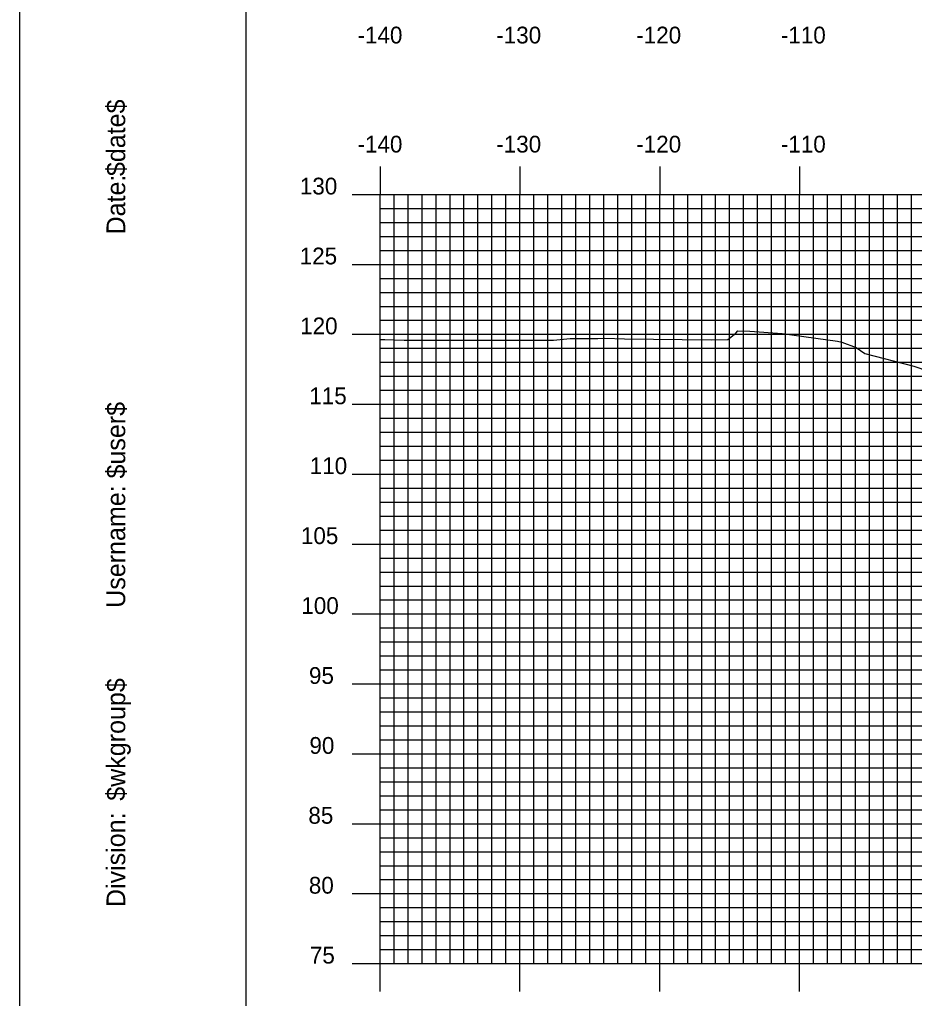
# Model space of a CAD drawing. Extents: x 856478 to 856821, y 364366 to 364586.
# Drawn here: x 856477.5 to 856541.5, y 364447.6 to 364517.6 of the extents above; entities that cross this region are included whole.
import ezdxf

# ---------------------------------------------------------------- set-up
doc = ezdxf.new("R2010")
doc.units = 0
for name, color, linetype in [('BORDER', 7, 'Continuous'), ('H_V ANNOTATION', 7, 'Continuous'), ('MAJOR', 7, 'Continuous'), ('MINOR', 7, 'Continuous'), ('PLOT BOUNDARY', 7, 'Continuous'), ('S_Roadway_Centerline', 7, 'Continuous')]:
    doc.layers.add(name, color=color, linetype=linetype)

msp = doc.modelspace()

# ---------------------------------------------------------------- linework, layer by layer
at = {"layer": 'BORDER'}
msp.add_lwpolyline([(856493.709, 364371.787), (856813.709, 364371.787), (856813.709, 364581.787), (856493.709, 364581.787)], close=True, dxfattribs=at)
at = {"layer": 'MAJOR'}
for p, q in [((856503.309, 364507.086), (856503.309, 364505.082)), ((856513.309, 364507.086), (856513.309, 364505.082)), ((856523.309, 364507.086), (856523.309, 364505.082)), ((856533.309, 364507.086), (856533.309, 364505.082)), ((856501.305, 364505.082), (856503.309, 364505.082)), ((856503.309, 364505.082), (856783.309, 364505.082)), ((856503.309, 364450.082), (856503.309, 364505.082)), ((856503.309, 364450.082), (856503.309, 364505.082)), ((856503.309, 364505.082), (856783.309, 364505.082)), ((856513.309, 364450.082), (856513.309, 364505.082)), ((856523.309, 364450.082), (856523.309, 364505.082)), ((856533.309, 364450.082), (856533.309, 364505.082)), ((856501.305, 364500.082), (856503.309, 364500.082)), ((856503.309, 364500.082), (856783.309, 364500.082)), ((856501.305, 364495.082), (856503.309, 364495.082)), ((856503.309, 364495.082), (856783.309, 364495.082)), ((856501.305, 364490.082), (856503.309, 364490.082)), ((856503.309, 364490.082), (856783.309, 364490.082)), ((856501.305, 364485.082), (856503.309, 364485.082)), ((856503.309, 364485.082), (856783.309, 364485.082)), ((856501.305, 364480.082), (856503.309, 364480.082)), ((856503.309, 364480.082), (856783.309, 364480.082)), ((856501.305, 364475.082), (856503.309, 364475.082)), ((856503.309, 364475.082), (856783.309, 364475.082)), ((856501.305, 364470.082), (856503.309, 364470.082)), ((856503.309, 364470.082), (856783.309, 364470.082)), ((856501.305, 364465.082), (856503.309, 364465.082)), ((856503.309, 364465.082), (856783.309, 364465.082)), ((856501.305, 364460.082), (856503.309, 364460.082)), ((856503.309, 364460.082), (856783.309, 364460.082)), ((856501.305, 364455.082), (856503.309, 364455.082)), ((856503.309, 364455.082), (856783.309, 364455.082)), ((856501.305, 364450.082), (856503.309, 364450.082)), ((856503.309, 364450.082), (856783.309, 364450.082)), ((856503.309, 364450.082), (856783.309, 364450.082)), ((856503.309, 364448.078), (856503.309, 364450.082)), ((856513.309, 364448.078), (856513.309, 364450.082)), ((856523.309, 364448.078), (856523.309, 364450.082)), ((856533.309, 364448.078), (856533.309, 364450.082))]:
    msp.add_line(p, q, dxfattribs=at)
at = {"layer": 'MINOR'}
for p, q in [((856503.309, 364450.082), (856503.309, 364505.082)), ((856504.309, 364450.082), (856504.309, 364505.082)), ((856505.309, 364450.082), (856505.309, 364505.082)), ((856506.309, 364450.082), (856506.309, 364505.082)), ((856507.309, 364450.082), (856507.309, 364505.082)), ((856508.309, 364450.082), (856508.309, 364505.082)), ((856509.309, 364450.082), (856509.309, 364505.082)), ((856510.309, 364450.082), (856510.309, 364505.082)), ((856511.309, 364450.082), (856511.309, 364505.082)), ((856512.309, 364450.082), (856512.309, 364505.082)), ((856514.309, 364450.082), (856514.309, 364505.082)), ((856515.309, 364450.082), (856515.309, 364505.082)), ((856516.309, 364450.082), (856516.309, 364505.082)), ((856517.309, 364450.082), (856517.309, 364505.082)), ((856518.309, 364450.082), (856518.309, 364505.082)), ((856519.309, 364450.082), (856519.309, 364505.082)), ((856520.309, 364450.082), (856520.309, 364505.082)), ((856521.309, 364450.082), (856521.309, 364505.082)), ((856522.309, 364450.082), (856522.309, 364505.082)), ((856524.309, 364450.082), (856524.309, 364505.082)), ((856525.309, 364450.082), (856525.309, 364505.082)), ((856526.309, 364450.082), (856526.309, 364505.082)), ((856527.309, 364450.082), (856527.309, 364505.082)), ((856528.309, 364450.082), (856528.309, 364505.082)), ((856529.309, 364450.082), (856529.309, 364505.082)), ((856530.309, 364450.082), (856530.309, 364505.082)), ((856531.309, 364450.082), (856531.309, 364505.082)), ((856532.309, 364450.082), (856532.309, 364505.082)), ((856534.309, 364450.082), (856534.309, 364505.082)), ((856535.309, 364450.082), (856535.309, 364505.082)), ((856536.309, 364450.082), (856536.309, 364505.082)), ((856537.309, 364450.082), (856537.309, 364505.082)), ((856538.309, 364450.082), (856538.309, 364505.082)), ((856539.309, 364450.082), (856539.309, 364505.082)), ((856540.309, 364450.082), (856540.309, 364505.082)), ((856541.309, 364450.082), (856541.309, 364505.082)), ((856503.309, 364504.082), (856783.309, 364504.082)), ((856503.309, 364504.082), (856505.313, 364504.082)), ((856503.309, 364503.082), (856783.309, 364503.082)), ((856503.309, 364503.082), (856505.313, 364503.082)), ((856503.309, 364502.082), (856783.309, 364502.082)), ((856503.309, 364502.082), (856505.313, 364502.082)), ((856503.309, 364501.082), (856783.309, 364501.082)), ((856503.309, 364501.082), (856505.313, 364501.082)), ((856503.309, 364499.082), (856783.309, 364499.082)), ((856503.309, 364499.082), (856505.313, 364499.082)), ((856503.309, 364498.082), (856783.309, 364498.082)), ((856503.309, 364498.082), (856505.313, 364498.082)), ((856503.309, 364497.082), (856783.309, 364497.082)), ((856503.309, 364497.082), (856505.313, 364497.082)), ((856503.309, 364496.082), (856783.309, 364496.082)), ((856503.309, 364496.082), (856505.313, 364496.082)), ((856503.309, 364494.082), (856783.309, 364494.082)), ((856503.309, 364494.082), (856505.313, 364494.082)), ((856503.309, 364493.082), (856783.309, 364493.082)), ((856503.309, 364493.082), (856505.313, 364493.082)), ((856503.309, 364492.082), (856783.309, 364492.082)), ((856503.309, 364492.082), (856505.313, 364492.082)), ((856503.309, 364491.082), (856783.309, 364491.082)), ((856503.309, 364491.082), (856505.313, 364491.082)), ((856503.309, 364489.082), (856783.309, 364489.082)), ((856503.309, 364489.082), (856505.313, 364489.082)), ((856503.309, 364488.082), (856783.309, 364488.082)), ((856503.309, 364488.082), (856505.313, 364488.082)), ((856503.309, 364487.082), (856783.309, 364487.082)), ((856503.309, 364487.082), (856505.313, 364487.082)), ((856503.309, 364486.082), (856783.309, 364486.082)), ((856503.309, 364486.082), (856505.313, 364486.082)), ((856503.309, 364484.082), (856783.309, 364484.082)), ((856503.309, 364484.082), (856505.313, 364484.082)), ((856503.309, 364483.082), (856783.309, 364483.082)), ((856503.309, 364483.082), (856505.313, 364483.082)), ((856503.309, 364482.082), (856783.309, 364482.082)), ((856503.309, 364482.082), (856505.313, 364482.082)), ((856503.309, 364481.082), (856783.309, 364481.082)), ((856503.309, 364481.082), (856505.313, 364481.082)), ((856503.309, 364479.082), (856783.309, 364479.082)), ((856503.309, 364479.082), (856505.313, 364479.082)), ((856503.309, 364478.082), (856783.309, 364478.082)), ((856503.309, 364478.082), (856505.313, 364478.082)), ((856503.309, 364477.082), (856783.309, 364477.082)), ((856503.309, 364477.082), (856505.313, 364477.082)), ((856503.309, 364476.082), (856783.309, 364476.082)), ((856503.309, 364476.082), (856505.313, 364476.082)), ((856503.309, 364474.082), (856783.309, 364474.082)), ((856503.309, 364474.082), (856505.313, 364474.082)), ((856503.309, 364473.082), (856783.309, 364473.082)), ((856503.309, 364473.082), (856505.313, 364473.082)), ((856503.309, 364472.082), (856783.309, 364472.082)), ((856503.309, 364472.082), (856505.313, 364472.082)), ((856503.309, 364471.082), (856783.309, 364471.082)), ((856503.309, 364471.082), (856505.313, 364471.082)), ((856503.309, 364469.082), (856783.309, 364469.082)), ((856503.309, 364469.082), (856505.313, 364469.082)), ((856503.309, 364468.082), (856783.309, 364468.082)), ((856503.309, 364468.082), (856505.313, 364468.082)), ((856503.309, 364467.082), (856783.309, 364467.082)), ((856503.309, 364467.082), (856505.313, 364467.082)), ((856503.309, 364466.082), (856783.309, 364466.082)), ((856503.309, 364466.082), (856505.313, 364466.082)), ((856503.309, 364464.082), (856783.309, 364464.082)), ((856503.309, 364464.082), (856505.313, 364464.082)), ((856503.309, 364463.082), (856783.309, 364463.082)), ((856503.309, 364463.082), (856505.313, 364463.082)), ((856503.309, 364462.082), (856783.309, 364462.082)), ((856503.309, 364462.082), (856505.313, 364462.082)), ((856503.309, 364461.082), (856783.309, 364461.082)), ((856503.309, 364461.082), (856505.313, 364461.082)), ((856503.309, 364459.082), (856783.309, 364459.082)), ((856503.309, 364459.082), (856505.313, 364459.082)), ((856503.309, 364458.082), (856783.309, 364458.082)), ((856503.309, 364458.082), (856505.313, 364458.082)), ((856503.309, 364457.082), (856783.309, 364457.082)), ((856503.309, 364457.082), (856505.313, 364457.082)), ((856503.309, 364456.082), (856783.309, 364456.082)), ((856503.309, 364456.082), (856505.313, 364456.082)), ((856503.309, 364454.082), (856783.309, 364454.082)), ((856503.309, 364454.082), (856505.313, 364454.082)), ((856503.309, 364453.082), (856783.309, 364453.082)), ((856503.309, 364453.082), (856505.313, 364453.082)), ((856503.309, 364452.082), (856783.309, 364452.082)), ((856503.309, 364452.082), (856505.313, 364452.082)), ((856503.309, 364451.082), (856783.309, 364451.082)), ((856503.309, 364451.082), (856505.313, 364451.082))]:
    msp.add_line(p, q, dxfattribs=at)
at = {"layer": 'PLOT BOUNDARY'}
msp.add_lwpolyline([(856477.523, 364365.669), (856817.523, 364365.669), (856817.523, 364585.669), (856477.523, 364585.669)], close=True, dxfattribs=at)
at = {"layer": 'S_Roadway_Centerline'}
msp.add_lwpolyline([(856503.309, 364494.705), (856503.654, 364494.707), (856505.028, 364494.675), (856515.715, 364494.669), (856516.911, 364494.778), (856518.884, 364494.785), (856519.374, 364494.803), (856520.788, 364494.761), (856526.98, 364494.682), (856528.187, 364494.704), (856528.747, 364495.172), (856528.887, 364495.328), (856529.751, 364495.303), (856532.067, 364495.141), (856536.03, 364494.6), (856536.338, 364494.514), (856537.36, 364494.147), (856537.983, 364493.706), (856541.476, 364492.802), (856549.508, 364490.06)], dxfattribs=at)

# ---------------------------------------------------------------- texts
at = {"layer": 'BORDER'}
for s, p in [('$date$', (856485.079, 364506.397)), ('Date:', (856485.079, 364502.221)), ('$user$', (856485.079, 364484.77)), ('Username:', (856485.079, 364475.523)), ('$wkgroup$', (856485.079, 364461.726)), ('Division:', (856485.079, 364454.119))]:
    msp.add_text(s, height=1.3392, rotation=90, dxfattribs=at).set_placement(p)
at = {"layer": 'H_V ANNOTATION'}
for s, p in [('-140', (856501.693, 364515.882)), ('-130', (856511.618, 364515.882)), ('-120', (856521.629, 364515.882)), ('-110', (856531.972, 364515.882)), ('-140', (856501.693, 364508.082)), ('-130', (856511.618, 364508.082)), ('-120', (856521.629, 364508.082)), ('-110', (856531.972, 364508.082)), ('130', (856497.569, 364505.082)), ('125', (856497.558, 364500.082)), ('120', (856497.59, 364495.082)), ('115', (856498.244, 364490.082)), ('110', (856498.276, 364485.082)), ('105', (856497.644, 364480.082)), ('100', (856497.676, 364475.082)), ('95', (856498.222, 364470.082)), ('90', (856498.254, 364465.082)), ('85', (856498.179, 364460.082)), ('80', (856498.211, 364455.082)), ('75', (856498.286, 364450.082))]:
    msp.add_text(s, height=1.2, dxfattribs=at).set_placement(p)
at = {"layer": 'MAJOR'}
msp.add_text('-', height=0.012, dxfattribs=at).set_placement((856503.3, 364450.082))

doc.saveas('drawing.dxf')
